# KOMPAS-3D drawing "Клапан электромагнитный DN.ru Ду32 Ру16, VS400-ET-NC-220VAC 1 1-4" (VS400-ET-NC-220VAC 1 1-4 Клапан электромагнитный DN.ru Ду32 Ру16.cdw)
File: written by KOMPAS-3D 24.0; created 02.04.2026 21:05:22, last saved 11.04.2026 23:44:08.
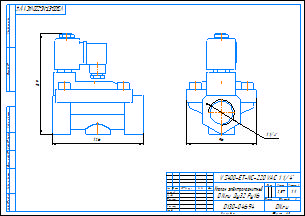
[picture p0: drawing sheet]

Document properties: c3d_UniqueCompID: ef56311e-7521-43dc-8291-0e6108b3d81d; Обозначение: VS400-ET-NC-220VAC 1; Наименование: Клапан электромагнитный DN.ru Ду25 Ру16; Автор: artio; Класс точности: c; Знак неуказанной шероховатости: Шероховатость не задана; Рассекать на разрезах: Да; c3d_UniqueCompID: ef56311e-7521-43dc-8291-0e6108b3d81d; Обозначение: VS400-ET-NC-220VAC 1-2; Наименование: Клапан электромагнитный DN.ru Ду15 Ру16; Автор: artio; Класс точности: c; Знак неуказанной шероховатости: Шероховатость не задана; Рассекать на разрезах: Да; c3d_UniqueCompID: ef56311e-7521-43dc-8291-0e6108b3d81d; Обозначение: VS400-ET-NC-220VAC 3-4; Наименование: Клапан электромагнитный DN.ru Ду20 Ру16; Автор: artio; Класс точности: c; Знак неуказанной шероховатости: Шероховатость не задана; Рассекать на разрезах: Да; c3d_UniqueCompID: ef56311e-7521-43dc-8291-0e6108b3d81d; Обозначение: VS400-ET-NC-220VAC 1 1-4; Наименование: Клапан электромагнитный DN.ru Ду32 Ру16; Автор: artio; Класс точности: c; Знак неуказанной шероховатости: Шероховатость не задана; Рассекать на разрезах: Да; c3d_UniqueCompID: ef56311e-7521-43dc-8291-0e6108b3d81d; Обозначение: VS400-ET-NC-220VAC 3-8; Наименование: Клапан электромагнитный DN.ru Ду10 Ру16; Автор: artio; Класс точности: c; Знак неуказанной шероховатости: Шероховатость не задана; Рассекать на разрезах: Да; Автор: artio; Форматы листов документа: A3; Полное имя файла: VS400-ET-NC-220VAC 1 1-4 Клапан электромагнитный DN.ru Ду32 Ру16.m3d; Масса: 2.569; Наименование: Клапан электромагнитный DN.ru Ду32 Ру16; Количество листов документа: 1; Примечание: D130-04694

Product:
- Body: Тело 1  | qty 1
    Масса: 4.144257
- Part/product: Клапан электромагнитный DN.ru Ду32 Ру16  | designation VS400-ET-NC-220VAC 1 1-4
    Масса: 2.569
    Раздел спецификации: Прочие изделия
    Примечание: D130-04694
    additional columns: ef56311e-7521-43dc-8291-0e6108b3d81d; VS400-ET-NC-220VAC 1 1-4; artio; c; Шероховатость не задана; Да

Views: Вид 1, Спереди
Referenced files in C:\Users\artio\OneDrive\Рабочий стол\Клапан электромагнитный DN.ru VS4x-xT-NC-x\DN10\: VS400-ET-NC-220VAC 3-8 Клапан электромагнитный DN.ru Ду10 Ру16.m3d, VS400-ET-NC-220VAC 3-8 Клапан электромагнитный DN.ru Ду10 Ру16.cdw
Referenced files in C:\Users\artio\OneDrive\Рабочий стол\Клапан электромагнитный DN.ru VS4x-xT-NC-x\DN32\: VS400-ET-NC-220VAC 1 1-4 Клапан электромагнитный DN.ru Ду32 Ру16.m3d
Referenced files in C:\Users\artio\OneDrive\Рабочий стол\Клапан электромагнитный DN.ru\VS400\VS400-ET-NC\VS400-ET-NC-220VAC\Ду32\: VS400-ET-NC-220VAC 1 1-4 Клапан электромагнитный DN.ru Ду32 Ру16.m3d
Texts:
  VS400-ET-NC-220VAC 1 1-4
  Клапан электромагнитный
  DN.ru Ду32 Ру16
  VS400-ET-NC-220VAC 1 1/4"
  VS400-ET-NC-220VAC 1 1/4"-
  Клапан электромагнитный DN.ru Ду32 Ру16
  VS400-ET-NC-220VAC 1 1-4 Клапан электромагнитный DN.ru Ду32 Ру16
Dimensions and other numbers on the sheet: 0; 3; 2; 4; 96; 1 1/4"; 1:1; 1; 2,57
